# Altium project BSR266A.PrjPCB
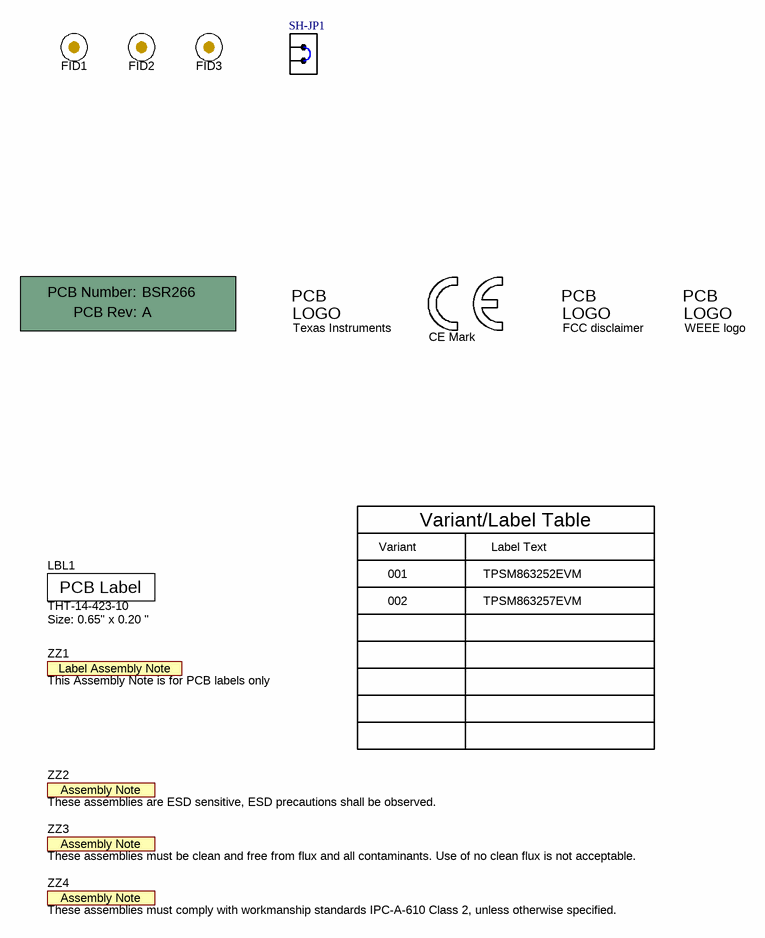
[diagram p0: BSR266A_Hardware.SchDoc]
CopyrightYear: 2022; PCB_Layout: Xueliang Zhang; PCB_Rev: A; PRJ_Customer: Public Release; PRJ_Engineer: Xueliang Zhang; PRJ_Number: BSR266; PRJ_Title: TPSM86x25xEVM; SCH_Rev: A; TechSupport: http://www.ti.com/support; TID: A0492431
2 sheets, 40 parts. Net scope: global (net labels, ports and power ports of the same name join across sheets).
Board file: BSR266A.PcbDoc
Sheets:
  BSR266A_Hardware.SchDoc
  BSR266A_Sch.SchDoc

## Sheet BSR266A_Hardware.SchDoc
size 431 x 279 mm; Date: Not shown in title block; ApprovedBy: Not shown in title block; CheckedBy: Not shown in title block; Author: Not shown in title block; CompanyName: Not shown in title block; Engineer: Not shown in title block; Organization: Not shown in title block; Address1: Not shown in title block; Address2: Not shown in title block; Address3: Not shown in title block; Address4: Not shown in title block; DocumentNumber: 3; Revision: Use project parameter SCH_Rev; SheetNumber: 3; SheetTotal: 3; PageSetup: Record=PageOptions¦CenterHorizontal=True¦CenterVertical=True¦PrintScale=1.00¦XCorrection=1.00¦YCorrection=1.00¦PrintKind=0¦BorderSize=5000000¦LeftOffset=0¦BottomOffset=0¦Orientation=2¦PaperLength=1000¦PaperWidth=1000¦Scale=100¦PaperSource=15¦PrintQuality=600¦MediaType=1¦DitherType=10¦PaperKind=Letter¦PrintScaleMode=1

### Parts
!PCB  Printed Circuit Board  (value not drawn)  (mechanical)
FID1  Fiducial  [Fiducial10-20]  (value not drawn)
FID2  Fiducial  [Fiducial10-20]  (value not drawn)
FID3  Fiducial  [Fiducial10-20]  (value not drawn)
LBL1  THT-14-423-10  Note: Size: 0.65" x 0.20 "  [Label_650x200]
Logo1  Texas Instruments  [TI_Stacked_Overlay_Small]  (no BOM)
Logo2  CE Mark  [CE_Mark_5mm]  (no BOM)
Logo3  FCC disclaimer  [FCC_disclaimer]  (no BOM)
Logo4  WEEE logo  [WEEE_Minimum]  (no BOM)
SH-JP1  SNT-100-BK-G  [SNT-100-BK-G]  (value not drawn)
ZZ1  This Assembly Note is for PCB labels only  [AssemblyNoteLabel]  (no BOM)
ZZ2  These assemblies are ESD sensitive, ESD precautions shall be observed.  [AssemblyNote]  (no BOM)
ZZ3  These assemblies must be clean and free from flux and all contaminants. Use of no clean flux is not acceptable.  [AssemblyNote]  (no BOM)
ZZ4  These assemblies must comply with workmanship standards IPC-A-610 Class 2, unless otherwise specified.  [AssemblyNote]  (no BOM)

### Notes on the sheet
- Variant
- Variant/Label Table
- Label Text
- 001
- 002
- TPSM863252EVM
- TPSM863257EVM

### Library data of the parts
!PCB = CMP-0003618-2: Manufacturer: Any; PartNumber: BSR266
FID1-FID3 = CMP-0077181-1: Fiducial mark.  There is nothing to buy or mount.
LBL1 = CMP-0003625-1: Thermal Transfer Printable Labels, 0.650" W x 0.200" H - 10,000 per roll; Manufacturer: Brady; CompType: Label
Logo1 = CMP-0074838-1: Texas Instrument Corporate Signature; SymbolCreator: a0412235; Lib Reference: TI_Logo; Library Reference: Logo
Logo2 = CMP-0074844-1: SymbolCreator: a0412235
Logo3 = CMP-0074847-1: FCC_disclaimer; Library Reference: Logo
Logo4 = CMP-0074769-1
SH-JP1 = CMP-0003623-1: Shunt, 100mil, Gold plated, Black; Alternate PartNumber: 969102-0000-DA; Manufacturer: Samtec; Alternate Manufacturer: 3M; Value: 1x2; Note: You can "mate" this to a header by matching the designator.  i.e. use SH-J3 for header J3
ZZ1 = CMP-0003616-3
ZZ2 = CMP-0077236-1
ZZ3 = CMP-0077237-1
ZZ4 = CMP-0077238-1

## Sheet BSR266A_Sch.SchDoc
size 431 x 279 mm; Date: Not shown in title block; ApprovedBy: Not shown in title block; CheckedBy: Not shown in title block; Author: Not shown in title block; CompanyName: Not shown in title block; Engineer: Not shown in title block; Organization: Not shown in title block; Address1: Not shown in title block; Address2: Not shown in title block; Address3: Not shown in title block; Address4: Not shown in title block; DocumentNumber: 2; Revision: Use project parameter SCH_Rev; SheetNumber: 2; SheetTotal: 3; PageSetup: Record=PageOptions¦CenterHorizontal=True¦CenterVertical=True¦PrintScale=1.00¦XCorrection=1.00¦YCorrection=1.00¦PrintKind=0¦BorderSize=5000000¦LeftOffset=0¦BottomOffset=0¦Orientation=2¦PaperLength=1000¦PaperWidth=1000¦Scale=100¦PaperSource=15¦PrintQuality=600¦MediaType=1¦DitherType=10¦PaperKind=Letter¦PrintScaleMode=1
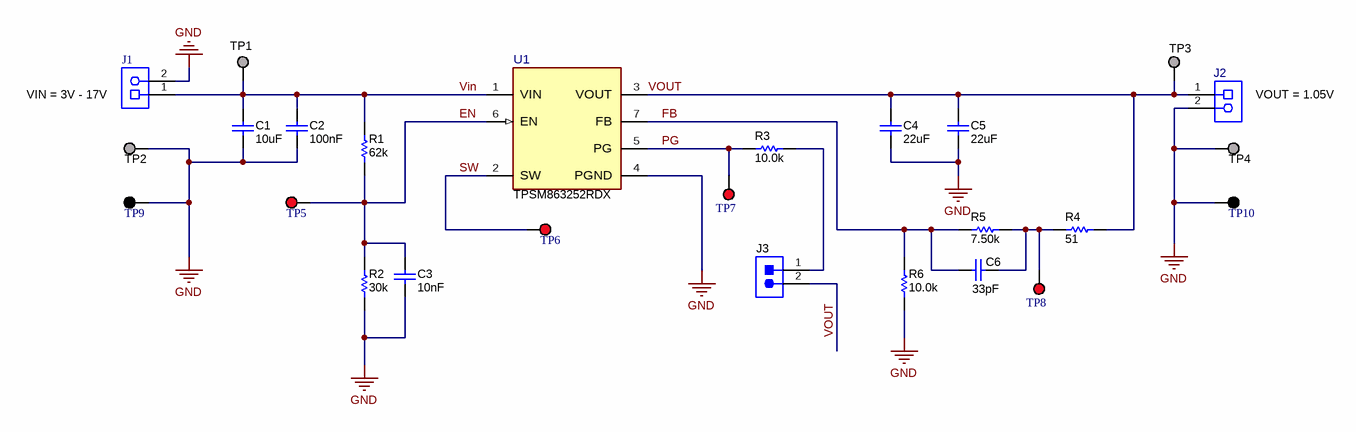
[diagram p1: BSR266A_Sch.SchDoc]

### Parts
C1  ValueDisplayed: 10uF  [0805_HV]  (hidden comment: GRM21BR61E106MA73L)
C2  Cap_F: 100nF  [0603]  (hidden comment: C0603C104K5RACTU)
C3  Cap_F: 10nF  [0603]  (hidden comment: C0603X103K5RACTU)
C4  ValueDisplayed: 22uF  [0805_HV]  (hidden comment: GRM21BC81C226ME44L)
C5  ValueDisplayed: 22uF  [0805_HV]  (hidden comment: GRM21BC81C226ME44L)
C6  ValueDisplayed: 33pF  [0603]  (hidden comment: GRM1885C2A330JA01D)
J1  ED120/2DS  [On-Shore_ED120_2DS]  (value not drawn)
J2  ED120/2DS  [On-Shore_ED120_2DS]  (value not drawn)
J3  PEC02SAAN  [CONN_PEC02SAAN]  (value not drawn)
R1  ValueDisplayed: 62k  [0603]  (hidden comment: CRCW060362K0JNEA)
R2  ValueDisplayed: 30k  [0603]  (hidden comment: CRCW060330K0JNEA)
R3  ValueDisplayed: 10.0k  [0603]  (hidden comment: CRCW060310K0FKEA)
R4  ValueDisplayed: 51  [0603]  (hidden comment: CRCW060351R0JNEA)
R5  ValueDisplayed: 7.50k  [0603]  (hidden comment: CRCW06037K50FKEA)
R6  ValueDisplayed: 10.0k  [0603]  (hidden comment: CRCW060310K0FKEA)
TP1  1502-2  [Keystone1502-2]  (value not drawn)
TP2  1502-2  [Keystone1502-2]  (value not drawn)
TP3  1502-2  [Keystone1502-2]  (value not drawn)
TP4  1502-2  [Keystone1502-2]  (value not drawn)
TP5  5000  [Keystone5000]  (value not drawn)
TP6  5000  [Keystone5000]  (value not drawn)
TP7  5000  [Keystone5000]  (value not drawn)
TP8  5000  [Keystone5000]  (value not drawn)
TP9  5001  [Keystone5001]  (value not drawn)
TP10  5001  [Keystone5001]  (value not drawn)
U1  TPSM863252RDX  [RDX0007A-MFG]

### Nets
GND: C1.2 C2.2 C3.2 C4.2 C5.2 J1.2 J2.2 R2.1 R6.1 TP2.1 TP4.1 TP9.1 TP10.1 U1.4(PGND)
EN: C3.1 R1.1 R2.2 TP5.1 U1.6(EN)
FB: C6.2 R5.1 R6.2 U1.7(FB)
PG: R3.1 TP7.1 U1.5(PG)
SW: TP6.1 U1.2(SW)
Vin: C1.1 C2.1 J1.1 R1.2 TP1.1 U1.1(VIN)
VOUT: C4.1 C5.1 J2.1 J3.2 R4.2 TP3.1 U1.3(VOUT)
NetC6_1: C6.1 R4.1 R5.2 TP8.1
NetJ3_1: J3.1 R3.2

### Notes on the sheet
- VIN = 3V - 17V
- VOUT = 1.05V

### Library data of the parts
C1 = CMP-0008303-3: CAP, CERM, 10 uF, 25 V, +/- 20%, X5R, 0805; Manufacturer: MuRata; SizeZ_mm: 1.45; U/M: EA; SizeAreaWB_mm2: 6.75; Value2: 25V; TaMin_C: -55°C; Value1: Unknown; Cap_F: 10µF; SizeX_mm: 2; Cap_Case: 0805; TaMax_C: 85°C; Polarized: N; SizeY_mm: 1.25; AEC Category: Q200; SizeArea_mm2: 2.5; Value: 10uF
C2 = CMP-0006861-3: CAP, CERM, 0.1 uF, 50 V, +/- 10%, X7R, 0603; Manufacturer: Kemet; TaMin_C: -55°C; Polarized: N; SizeAreaWB_mm2: 4.68; Value1: Unknown; U/M: EA; Value: 0.1uF; TaMax_C: 125°C; SizeZ_mm: 1; SizeX_mm: 1.6; SizeY_mm: 0.8; Value2: 50V; SizeArea_mm2: 1.28; AEC Category: Q200
C3 = CMP-0006978-1: CAP, CERM, 0.01 uF, 50 V, +/- 10%, X7R, 0603; Manufacturer: Kemet; TaMin_C: -55°C; Polarized: N; SizeAreaWB_mm2: 4.68; Value1: Unknown; U/M: EA; Value: 0.01uF; TaMax_C: 125°C; SizeZ_mm: 1; SizeX_mm: 1.6; SizeY_mm: 0.8; Value2: 50V; SizeArea_mm2: 1.28; AEC Category: Q200
C4 C5 = CMP-0008269-1: CAP, CERM, 22 uF, 16 V, +/- 20%, X6S, 0805; Manufacturer: MuRata; TaMin_C: -55°C; Polarized: N; SizeAreaWB_mm2: 6.75; Value1: Unknown; U/M: EA; Value: 22uF; TaMax_C: 105°C; SizeZ_mm: 1.45; SizeX_mm: 2; SizeY_mm: 1.25; Cap_Case: 0805; Value2: 16V; SizeArea_mm2: 2.5; Cap_F: 22µF; AEC Category: Q200
C6 = CMP-0007263-3: CAP, CERM, 33 pF, 100 V, +/- 5%, C0G/NP0, 0603; Manufacturer: MuRata; TaMin_C: -55°C; Polarized: N; SizeAreaWB_mm2: 4.68; Value1: Unknown; U/M: EA; Value: 33pF; TaMax_C: 125°C; SizeZ_mm: 1; SizeX_mm: 1.6; SizeY_mm: 0.8; Value2: 100V; SizeArea_mm2: 1.28; AEC Category: Q200
J1 J2 = CMP-0074910-1: Terminal Block, 5.08 mm, 2x1, Brass, TH; Manufacturer: On-Shore Technology; Pitch_mm: 5.08; Gender: Female; Shrouded: N; Row_Count: 1; Current_A: 15A; Voltage_V: 300V; Cert_CULUS: Y; CNHeader: False; CT: True; Green_Lifecycle: Not Set; Green_REACh: Incomplete
J3 = CMP-0002337-1: Header, 100mil, 2x1, Tin, TH; Manufacturer: Sullins Connector Solutions; CNHeader: TRUE; Current_A: 3A; Green_Lifecycle: Not Set; Shrouded: N; Gender: Male; Green_REACh: Incomplete; Voltage_V: 1.8kV; Row_Count: 1; Pitch_mm: 2.54; CT: FALSE; Cert_UL: Y
R1 = CMP-0025838-3: RES, 62 k, 5%, 0.1 W, 0603; Manufacturer: Vishay-Dale; Power_W: 100mW; TempCo: 200 ppm/C; Value_Code: 62k0; U/M: EA; Value: 62k; EIA_Code: E24; SizeX_mm: 1.6; SizeY_mm: 0.8; SizeZ_mm: 1; Value2: 0.1W; SizeArea_mm2: 1.28; VDC_V: 75V; AEC Category: Q200
R2 = CMP-0025782-1: RES, 30 k, 5%, 0.1 W, 0603; Manufacturer: Vishay-Dale; Power_W: 100mW; TempCo: 200 ppm/C; Value_Code: 30k0; U/M: EA; Value: 30k; EIA_Code: E24; SizeX_mm: 1.6; SizeY_mm: 0.8; SizeZ_mm: 1; Value2: 0.1W; SizeArea_mm2: 1.28; VDC_V: 75V; AEC Category: Q200
R3 R6 = CMP-0021998-2: RES, 10.0 k, 1%, 0.1 W, 0603; Manufacturer: Vishay-Dale; Power_W: 100mW; TempCo: 100 ppm/C; Value_Code: 10k0; U/M: EA; Value: 10.0k; EIA_Code: E96; Res_ohm: 10k; SizeX_mm: 1.6; SizeY_mm: 0.8; SizeZ_mm: 1; Value2: 0.1W; SizeArea_mm2: 1.28; VDC_V: 75V; AEC Category: Q200
R4 = CMP-0025825-2: RES, 51, 5%, 0.1 W, 0603; Manufacturer: Vishay-Dale; Power_W: 100mW; TempCo: 200 ppm/C; Value_Code: 51R0; U/M: EA; Value: 51; EIA_Code: E24; SizeX_mm: 1.6; SizeY_mm: 0.8; SizeZ_mm: 1; Value2: 0.1W; SizeArea_mm2: 1.28; VDC_V: 75V; AEC Category: Q200
R5 = CMP-0022601-1: RES, 7.50 k, 1%, 0.1 W, 0603; Manufacturer: Vishay-Dale; Power_W: 100mW; TempCo: 100 ppm/C; Value_Code: 7k50; U/M: EA; Value: 7.50k; EIA_Code: E96; Res_ohm: 7.5k; SizeX_mm: 1.6; SizeY_mm: 0.8; SizeZ_mm: 1; Value2: 0.1W; SizeArea_mm2: 1.28; VDC_V: 75V; AEC Category: Q200
TP1-TP4 = CMP-0055113-1: Terminal, Turret, TH, Double; Manufacturer: Keystone; CT: FALSE; Green_REACh: Passed; CompType: Turret Terminal; Green_Lifecycle: Active
TP5-TP8 = CMP-0055137-1: Test Point, Miniature, Red, TH; Manufacturer: Keystone; CNHeader: FALSE; Green_Lifecycle: Active; Green_REACh: Passed; ContactFinish: Silver; CT: TRUE
TP9 TP10 = CMP-0055138-1: Test Point, Miniature, Black, TH; Manufacturer: Keystone; CNHeader: FALSE; Green_Lifecycle: Active; Green_REACh: Passed; ContactFinish: Silver; CT: TRUE
U1 = CMP-0097277-1: 3V to 16 V Input, 3-A Synchronous Step-Down Voltage Regulator Module, QFN-FCMOD7; Manufacturer: Texas Instruments; Nominal Supply Current: 120-400uA; SizeZ_mm: 2.1mm; AEC Qualified: No; Output Type: AdjustableProgrammable; Switching Topology: Buck; AEC Grade: NA; Standoff Height: 0mm; Max Supply Voltage: 16V; Number Of Outputs: 1; Switching Frequency: 1400/2000kHz; TJmax_C: +125°C; Max Duty Cycle: 98%; Output Voltage: 0.6-7V

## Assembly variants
001: not fitted C5 C6
002: not fitted C5 C6; alternate parts U1 -> CMP-0097279-1
003: not fitted C5 C6 R6; alternate parts R5 -> CMP-0025885-5, U1 -> CMP-0097278-1
004: not fitted C5 C6 R6; alternate parts R5 -> CMP-0025885-5, U1 -> CMP-0048973-1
